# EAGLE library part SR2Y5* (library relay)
Safety Relay 2 pole 6 A SCHRACK Source: http://www.schrack.com/.. 5809.pdf
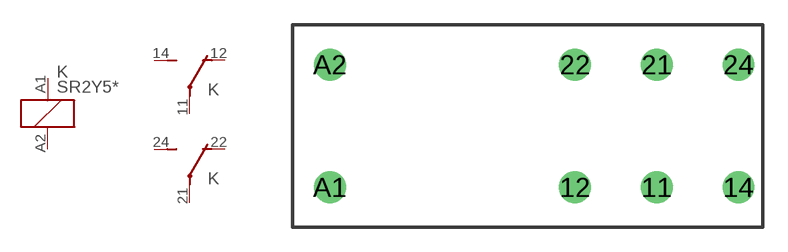
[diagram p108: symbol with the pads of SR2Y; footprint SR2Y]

Designator prefix K; gates 1=K 2=U 3=U

## SR2Y5005 (OC_FARNELL: unknown; OC_NEWARK: unknown), SR2Y5006 (OC_FARNELL: unknown; OC_NEWARK: unknown), SR2Y5009 (OC_FARNELL: unknown; OC_NEWARK: unknown), SR2Y5012 (OC_FARNELL: unknown; OC_NEWARK: unknown), SR2Y5018 (OC_FARNELL: unknown; OC_NEWARK: unknown), SR2Y5021 (OC_FARNELL: unknown; OC_NEWARK: unknown), SR2Y5024 (OC_FARNELL: unknown; OC_NEWARK: unknown), SR2Y5036 (OC_FARNELL: unknown; OC_NEWARK: unknown), SR2Y5040 (OC_FARNELL: unknown; OC_NEWARK: unknown), SR2Y5048 (OC_FARNELL: unknown; OC_NEWARK: unknown), SR2Y5060 (OC_FARNELL: unknown; OC_NEWARK: unknown), SR2Y5080 (OC_FARNELL: unknown; OC_NEWARK: unknown), SR2Y5110 (OC_FARNELL: unknown; OC_NEWARK: unknown)  [SR2Y]
11  2:P  pas
12  2:O  pas
14  2:S  pas
21  3:P  pas
22  3:O  pas
24  3:S  pas
A1  1:1  pas
A2  1:2  pas

## Footprint SR2Y (pad centres in mm)
Safety Relay 2 pole 6 A SCHRACK Source: http://www.schrack.com/.. 5809.pdf
drill 1.3 round: 11 7.54,-3.75; 12 2.54,-3.75; 14 12.54,-3.75; 21 7.54,3.75; 22 2.54,3.75; 24 12.54,3.75; A1 -12.46,-3.75; A2 -12.46,3.75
